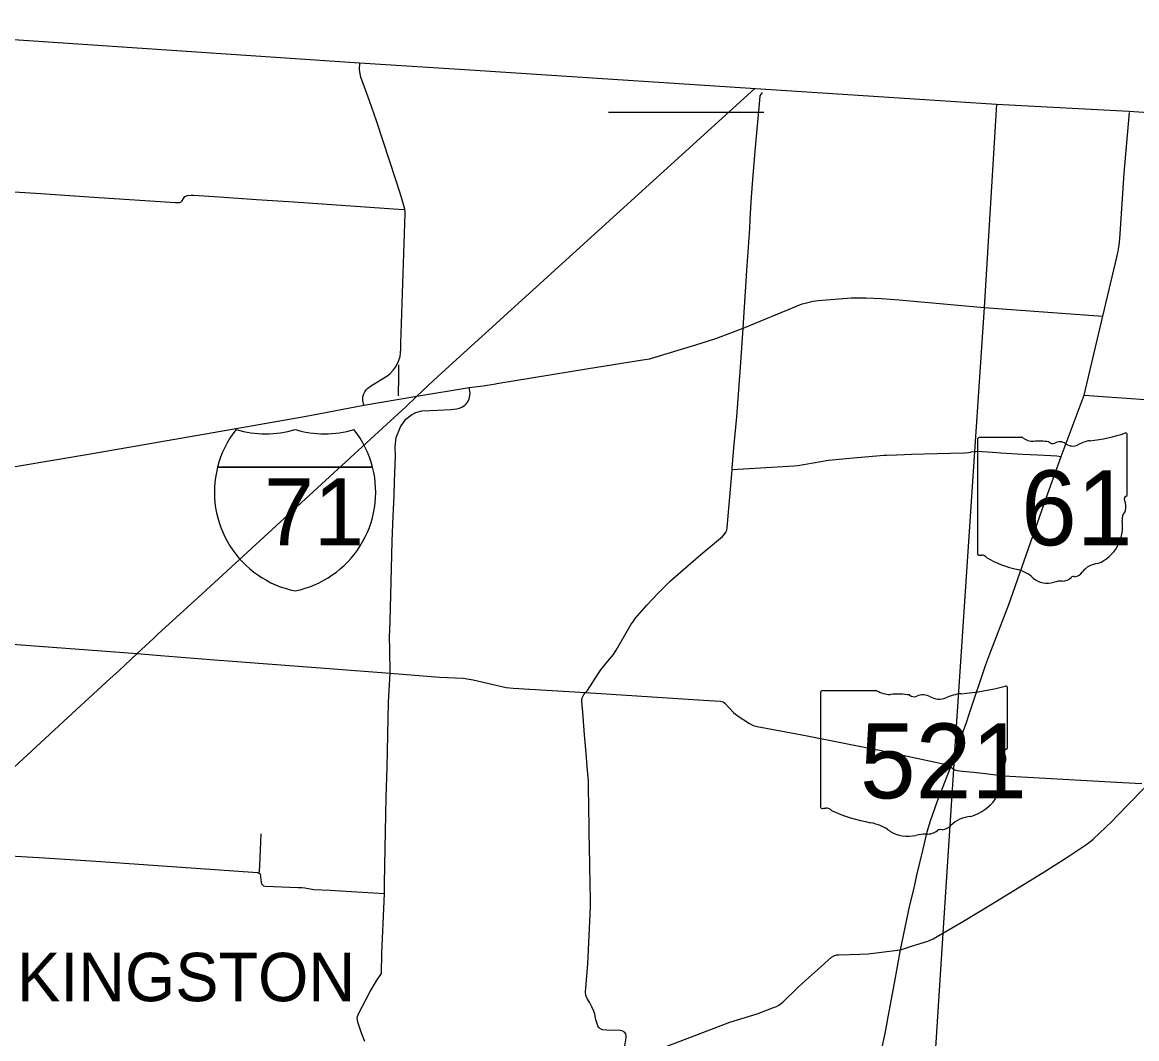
# Model space of a CAD drawing. Extents: x 1729596 to 1925846, y 659247 to 911751.
# Drawn here: x 1855559 to 1876281, y 840189 to 859080 of the extents above; entities that cross this region are included whole.
import ezdxf

# ---------------------------------------------------------------- set-up
doc = ezdxf.new("R2010")
doc.units = 0
for name, color, linetype in [('GM_X_County', 7, 'Continuous'), ('GM_X_County_Road', 7, 'Continuous'), ('GM_X_Interstate_Route', 7, 'Continuous'), ('GM_X_Interstate_Shield', 7, 'Continuous'), ('GM_X_State_Route', 7, 'Continuous'), ('GM_X_State_Shield', 7, 'Continuous'), ('GM_X_Township', 7, 'Continuous'), ('GM_X_Township_Road', 7, 'Continuous'), ('GM_X_Township_Text', 7, 'Continuous')]:
    doc.layers.add(name, color=color, linetype=linetype)

msp = doc.modelspace()

# ---------------------------------------------------------------- linework, layer by layer
at = {"layer": 'GM_X_County'}
msp.add_lwpolyline([(1850615, 859080), (1861827, 858324), (1863977, 858188), (1869100, 857855), (1873671, 857558), (1876143, 857428), (1879641, 857188)], dxfattribs=at)
at = {"layer": 'GM_X_County_Road'}
for points in [[(1864382, 852364), (1866086, 852648), (1867135, 852815), (1867230, 852828), (1867285, 852844), (1868084, 853084), (1868453, 853203), (1868961, 853395), (1869281, 853526), (1870063, 853845), (1870117, 853862), (1870213, 853886), (1870261, 853896), (1870358, 853911), (1870972, 853957), (1871252, 853958), (1871532, 853946), (1871862, 853920), (1872960, 853823), (1873374, 853784)], [(1873374, 853784), (1873447, 853777), (1875479, 853633), (1875652, 853621)], [(1861908, 851967), (1862897, 852129), (1863869, 852294), (1864131, 852325), (1864358, 852360), (1864382, 852364)], [(1862398, 846985), (1862393, 847427), (1862390, 847645), (1862398, 847952), (1862426, 848926), (1862437, 849437), (1862456, 849903), (1862475, 850277), (1862478, 850547), (1862493, 850863), (1862501, 851015), (1862495, 851192), (1862512, 851365), (1862591, 851559), (1862689, 851703), (1862793, 851783), (1862874, 851825), (1862991, 851861), (1863286, 851873), (1863528, 851886), (1863641, 851896), (1863689, 851908), (1863745, 851933), (1863788, 851965), (1863815, 851990), (1863841, 852025), (1863866, 852082), (1863882, 852144), (1863886, 852190), (1863869, 852294)], [(1851992, 850242), (1853696, 850524), (1855503, 850836), (1856828, 851059), (1859214, 851472), (1860807, 851754), (1861908, 851967)], [(1861929, 840138), (1861858, 840312), (1861805, 840480), (1861790, 840535), (1861787, 840580), (1861813, 840652), (1862029, 841063), (1862144, 841266), (1862236, 841398), (1862246, 841780), (1862289, 842748), (1862292, 842889), (1862296, 843070), (1862302, 843409), (1862314, 844036), (1862323, 844679), (1862341, 845231), (1862369, 846442), (1862398, 846985)]]:
    msp.add_lwpolyline(points, dxfattribs=at)
at = {"layer": 'GM_X_Interstate_Route'}
for points in [[(1863205, 852422), (1863294, 852506), (1869179, 857847)], [(1862551, 851804), (1862690, 851932), (1862897, 852129), (1863205, 852422)], [(1858003, 847635), (1858079, 847705), (1858902, 848457), (1860588, 850008), (1861123, 850496), (1862182, 851466), (1862551, 851804)], [(1857351, 847028), (1857695, 847346), (1858003, 847635)], [(1853497, 843457), (1854091, 844035), (1854810, 844689), (1856408, 846161), (1857196, 846884), (1857351, 847028)]]:
    msp.add_lwpolyline(points, dxfattribs=at)
at = {"layer": 'GM_X_Interstate_Shield'}
for p, q in [((1866460, 857408), (1869345, 857408)), ((1859188, 850809), (1862074, 850809)), ((1862074, 850809), (1859188, 850809)), ((1862074, 850809), (1859188, 850809))]:
    msp.add_line(p, q, dxfattribs=at)
for centre, start, end in [((1861006, 850349), 141.669, 165.8066), ((1860083, 853306), 253.0091, 286.9909), ((1861179, 853306), 253.0091, 286.9909), ((1860256, 850349), 14.1934, 38.331), ((1861006, 850349), 165.8066, 258.463), ((1860256, 850349), 281.537, 14.1934)]:
    msp.add_arc(centre, 1875, start, end, dxfattribs=at)
at = {"layer": 'GM_X_State_Route'}
for points in [[(1871531, 839946), (1871607, 840316), (1871659, 840595), (1871776, 841222), (1871888, 841839), (1872065, 842672), (1872135, 842960), (1872195, 843231), (1872309, 843713), (1872385, 844033), (1872444, 844239), (1872573, 844591), (1872823, 845242), (1872889, 845433), (1872993, 845731), (1873113, 846066), (1873172, 846240), (1873478, 847144), (1873548, 847343), (1873901, 848259), (1874595, 850236), (1874875, 851008), (1875301, 852152), (1875652, 853621), (1875910, 854713), (1875935, 854825), (1875954, 854939), (1875967, 855054), (1876050, 856275), (1876144, 857406)], [(1853462, 847664), (1857695, 847346), (1858127, 847314), (1859061, 847239), (1861267, 847070), (1862398, 846985), (1863319, 846906), (1863758, 846887), (1863941, 846861), (1864557, 846719), (1864687, 846705), (1866030, 846621), (1868225, 846483), (1868543, 846460), (1868589, 846449), (1868624, 846426), (1868784, 846250), (1868850, 846195), (1869082, 846046), (1869152, 846012), (1869221, 845989), (1869925, 845860), (1870186, 845810), (1871499, 845553), (1872455, 845346), (1872684, 845295), (1872802, 845263), (1872823, 845242), (1872874, 845201), (1872899, 845188), (1872917, 845181), (1872945, 845174), (1873042, 845161), (1873246, 845142), (1873416, 845122), (1873807, 845072), (1875906, 844954), (1876379, 844930)], [(1875906, 844320), (1876154, 844572), (1876386, 844812), (1876497, 844924), (1876868, 845210), (1877089, 845378), (1877250, 845505), (1877281, 845529), (1877348, 845583), (1877908, 846019)], [(1871888, 841839), (1872092, 841906), (1872394, 841999), (1872499, 842046), (1872678, 842151), (1873057, 842376), (1873560, 842674), (1874539, 843277), (1875001, 843568), (1875337, 843791), (1875406, 843841), (1875471, 843896), (1875822, 844235), (1875906, 844320)]]:
    msp.add_lwpolyline(points, dxfattribs=at)
at = {"layer": 'GM_X_State_Shield'}
for p, q in [((1873321, 851323), (1873321, 849210)), ((1873321, 851323), (1873321, 849210)), ((1874164, 851360), (1873349, 851360)), ((1874164, 851360), (1873349, 851360)), ((1876105, 850307), (1876105, 851412)), ((1876105, 850307), (1876105, 851412)), ((1876105, 850307), (1876105, 850307)), ((1876105, 850307), (1876105, 850307)), ((1873878, 845603), (1873878, 846708)), ((1873878, 845603), (1873878, 846708)), ((1870398, 846620), (1870398, 844506)), ((1870398, 846620), (1870398, 844506)), ((1871452, 846656), (1870432, 846656)), ((1871452, 846656), (1870432, 846656)), ((1873878, 845603), (1873878, 845603)), ((1873878, 845603), (1873878, 845603))]:
    msp.add_line(p, q, dxfattribs=at)
for centre, radius, start, end in [((1873353, 851328), 32.3, 98.1301, 188.1301), ((1873353, 851328), 32.3, 98.1301, 188.1301), ((1874358, 851605), 313, 231.6195, 271.1119), ((1874358, 851605), 313, 231.6195, 271.1119), ((1874462, 850173), 1123, 80.4867, 94.9883), ((1874462, 850173), 1123, 80.4867, 94.9883), ((1874717, 851339), 90.3, 219.7921, 297.1024), ((1874717, 851339), 90.3, 219.7921, 297.1024), ((1874849, 851095), 188, 54.4667, 119.1411), ((1874849, 851095), 188, 54.4667, 119.1411), ((1875490, 850714), 594, 97.3462, 120.7689), ((1875490, 850714), 594, 97.3462, 120.7689), ((1875114, 854241), 2953, 275.8445, 288.9065), ((1875114, 854241), 2953, 275.8445, 288.9065), ((1876075, 851417), 31, 351.8621, 97.738), ((1876075, 851417), 31, 351.8621, 97.738), ((1875092, 851430), 226, 233.8562, 294.8282), ((1875092, 851430), 226, 233.8562, 294.8282), ((1876098, 850225), 48, 107.944, 210.337), ((1876098, 850225), 48, 107.944, 210.337), ((1876072, 850302), 33.2, 289.6038, 7.7341), ((1876072, 850302), 33.2, 289.6038, 7.7341), ((1875793, 850086), 288, 340.033, 23.6496), ((1875793, 850086), 288, 340.033, 23.6496), ((1875279, 849703), 739, 292.3089, 8.9858), ((1875279, 849703), 739, 292.3089, 8.9858), ((1876217, 849844), 210, 136.8065, 186.9296), ((1876217, 849844), 210, 136.8065, 186.9296), ((1873353, 849205), 32.5, 171.9584, 258.3066), ((1873353, 849205), 32.5, 171.9584, 258.3066), ((1873358, 849422), 248, 267.339, 280.6039), ((1873358, 849422), 248, 267.339, 280.6039), ((1873409, 849088), 89.5, 29.7484, 93.2717), ((1873409, 849088), 89.5, 29.7484, 93.2717), ((1874540, 850987), 2132, 240.4129, 257.1985), ((1874540, 850987), 2132, 240.4129, 257.1985), ((1875590, 848617), 404, 94.4031, 142.5768), ((1875590, 848617), 404, 94.4031, 142.5768), ((1873904, 848261), 667, 47.1842, 75.836), ((1873904, 848261), 667, 47.1842, 75.836), ((1875105, 848715), 63.5, 65.7517, 132.6484), ((1875105, 848715), 63.5, 65.7517, 132.6484), ((1875078, 849005), 239, 282.8732, 323.2771), ((1875078, 849005), 239, 282.8732, 323.2771), ((1874625, 849078), 423, 230.7004, 286.2918), ((1874625, 849078), 423, 230.7004, 286.2918), ((1874870, 848347), 348, 85.6951, 111.2099), ((1874870, 848347), 348, 85.6951, 111.2099), ((1874901, 848919), 226, 268.777, 315.5493), ((1874901, 848919), 226, 268.777, 315.5493)]:
    msp.add_arc(centre, radius, start, end, dxfattribs=at)
for centre, major_axis, start_param, end_param in [((1872639, 849537), (3691, 0), 4.814394, 5.042369), ((1872639, 849537), (3691, 0), 4.814394, 5.042369), ((1873840, 846713), (38.7, 0), 6.141152, 7.989035), ((1873840, 846713), (38.7, 0), 6.141152, 7.989035), ((1870438, 846624), (40.3, 0), 1.712693, 3.28349), ((1870438, 846624), (40.3, 0), 1.712693, 3.28349), ((1871694, 846901), (391, 0), 4.042523, 4.731795), ((1871694, 846901), (391, 0), 4.042523, 4.731795), ((1871824, 845470), (1404, 0), 1.404758, 1.657858), ((1871824, 845470), (1404, 0), 1.404758, 1.657858), ((1872143, 846635), (113, 0), 3.836095, 5.185415), ((1872143, 846635), (113, 0), 3.836095, 5.185415), ((1872308, 846391), (235, 0), 0.950623, 2.079405), ((1872308, 846391), (235, 0), 0.950623, 2.079405), ((1872611, 846726), (282, 0), 4.081561, 5.145723), ((1872611, 846726), (282, 0), 4.081561, 5.145723), ((1873109, 846011), (743, 0), 1.699011, 2.107814), ((1873109, 846011), (743, 0), 1.699011, 2.107814), ((1873870, 845522), (60, 0), 1.883978, 3.671073), ((1873870, 845522), (60, 0), 1.883978, 3.671073), ((1873488, 845382), (360, 0), 5.934695, 6.695948), ((1873488, 845382), (360, 0), 5.934695, 6.695948), ((1873837, 845599), (41.5, 0), 5.05454, 6.418171), ((1873837, 845599), (41.5, 0), 5.05454, 6.418171), ((1874017, 845140), (262, 0), 2.387724, 3.262537), ((1874017, 845140), (262, 0), 2.387724, 3.262537), ((1872845, 845000), (923, 0), 5.101752, 6.440018), ((1872845, 845000), (923, 0), 5.101752, 6.440018), ((1870438, 844502), (40.7, 0), 3.00124, 4.508301), ((1870438, 844502), (40.7, 0), 3.00124, 4.508301), ((1870444, 844718), (310, 0), 4.665946, 4.897461), ((1870444, 844718), (310, 0), 4.665946, 4.897461), ((1870508, 844385), (112, 0), 0.519207, 1.627899), ((1870508, 844385), (112, 0), 0.519207, 1.627899), ((1871921, 846283), (2665, 0), 4.195997, 4.488961), ((1871921, 846283), (2665, 0), 4.195997, 4.488961), ((1873235, 843913), (506, 0), 1.647645, 2.488434), ((1873235, 843913), (506, 0), 1.647645, 2.488434), ((1871127, 843557), (834, 0), 0.823519, 1.323587), ((1871127, 843557), (834, 0), 0.823519, 1.323587), ((1872028, 844374), (529, 0), 4.026481, 4.996735), ((1872028, 844374), (529, 0), 4.026481, 4.996735), ((1872373, 844216), (282, 0), 4.691044, 5.507374), ((1872373, 844216), (282, 0), 4.691044, 5.507374), ((1872628, 844011), (79.4, 0), 1.147584, 2.315152), ((1872628, 844011), (79.4, 0), 1.147584, 2.315152), ((1872594, 844302), (298, 0), 4.937069, 5.64225), ((1872594, 844302), (298, 0), 4.937069, 5.64225), ((1872334, 843643), (435, 0), 1.495662, 1.94098), ((1872334, 843643), (435, 0), 1.495662, 1.94098)]:
    msp.add_ellipse(centre, major_axis=major_axis, ratio=0.8, start_param=start_param, end_param=end_param, dxfattribs=at)
at = {"layer": 'GM_X_Township'}
msp.add_lwpolyline([(1850615, 859080), (1861827, 858324), (1863977, 858188), (1869100, 857855), (1873671, 857558), (1873447, 853777), (1873266, 851105), (1872889, 845433), (1872874, 845201), (1872678, 842151), (1872497, 839344), (1872306, 836385), (1871965, 831096), (1871301, 831135), (1870943, 831158), (1868637, 831266), (1861106, 831707), (1859467, 831803), (1858606, 831851), (1854821, 832136)], dxfattribs=at)
at = {"layer": 'GM_X_Township_Road'}
for points in [[(1862600, 853109), (1862679, 855525), (1862678, 855551), (1862670, 855604), (1862621, 855781), (1862579, 855924), (1862511, 856133), (1862144, 857247), (1862016, 857620), (1861855, 858062), (1861842, 858124), (1861831, 858202), (1861835, 858314)], [(1869094, 855406), (1869114, 855750), (1869148, 856242), (1869190, 856752), (1869276, 857636), (1869281, 857713), (1869320, 857773)], [(1851052, 856192), (1851109, 856192), (1851317, 856179), (1852272, 856121), (1852677, 856096), (1855405, 855928), (1855903, 855897), (1856892, 855832)], [(1856892, 855832), (1858408, 855732), (1858481, 855729), (1858507, 855738), (1858528, 855753), (1858558, 855806), (1858584, 855843), (1858630, 855863), (1858699, 855865), (1858740, 855866), (1859219, 855834), (1859911, 855789), (1860608, 855745), (1862639, 855602), (1862670, 855604)], [(1868961, 853395), (1869030, 854466), (1869084, 855249), (1869094, 855406)], [(1866125, 842638), (1866122, 842825), (1866119, 843014), (1866110, 843448), (1866102, 844029), (1866096, 844587), (1866090, 844777), (1866088, 844973), (1866065, 845250), (1866043, 845495), (1866013, 845838), (1865981, 846259), (1865967, 846390), (1865963, 846470), (1865970, 846524), (1865985, 846563), (1865999, 846589), (1866030, 846621), (1866069, 846663), (1866266, 846968), (1866317, 847046), (1866389, 847138), (1866477, 847243), (1866553, 847332), (1866604, 847408), (1866882, 847892), (1866909, 847933), (1866956, 847998), (1867172, 848249), (1867375, 848465), (1867610, 848696), (1868175, 849189), (1868579, 849525), (1868618, 849565), (1868643, 849606), (1868658, 849643), (1868666, 849690), (1868752, 850688), (1868758, 850767), (1868760, 850792), (1868792, 851171), (1868844, 851750), (1868884, 852250), (1868920, 852760), (1868961, 853395)], [(1861908, 851967), (1861890, 852053), (1861889, 852074), (1861893, 852116), (1861897, 852136), (1861910, 852176), (1861929, 852213), (1861940, 852231), (1861953, 852247), (1861967, 852263), (1861987, 852281), (1862055, 852330), (1862353, 852513), (1862401, 852552), (1862464, 852620), (1862501, 852670), (1862532, 852724), (1862557, 852780), (1862583, 852869), (1862593, 852930), (1862597, 853012), (1862600, 853109)], [(1862555, 852138), (1862563, 852502), (1862563, 852712)], [(1875301, 852152), (1877831, 851971)], [(1871629, 851035), (1871821, 851038), (1872096, 851051), (1872573, 851066), (1873080, 851077), (1873153, 851086), (1873189, 851092), (1873201, 851094)], [(1873201, 851094), (1873266, 851105), (1873316, 851109), (1873602, 851093), (1873755, 851081), (1874156, 851056), (1874440, 851043), (1874686, 851029), (1874797, 851021), (1874875, 851008)], [(1868758, 850767), (1869911, 850836), (1869979, 850842), (1870548, 850939), (1871084, 850990), (1871587, 851034), (1871629, 851035)], [(1859959, 843268), (1859968, 843303), (1859973, 843410), (1859989, 843698), (1860002, 843997)], [(1854896, 843613), (1855969, 843548), (1857017, 843480), (1859932, 843277), (1859959, 843268), (1859973, 843260), (1859980, 843245), (1860002, 843098), (1860009, 843067), (1860041, 843030), (1860074, 843024), (1860686, 842999), (1860758, 842996), (1860814, 842991), (1860981, 842964), (1861282, 842947), (1861478, 842937), (1862292, 842889)], [(1866765, 840057), (1866786, 840206), (1866788, 840245), (1866781, 840280), (1866759, 840313), (1866716, 840336), (1866676, 840340), (1866424, 840347), (1866350, 840355), (1866320, 840364), (1866299, 840377), (1866280, 840396), (1866263, 840426), (1866226, 840542), (1866202, 840647), (1866186, 840698), (1866148, 840779), (1866109, 840853), (1866060, 840934), (1866038, 840989), (1866033, 841051), (1866073, 841581), (1866099, 842105), (1866125, 842638)], [(1866665, 839615), (1866674, 839624), (1866777, 839711), (1866913, 839811), (1868052, 840243), (1868716, 840498), (1869221, 840653), (1869529, 840766), (1869582, 840790), (1869627, 840814), (1869702, 840869), (1869986, 841148), (1870122, 841273), (1870349, 841472), (1870605, 841706), (1870651, 841731), (1870706, 841746), (1870745, 841748), (1871135, 841758), (1871285, 841769), (1871833, 841832), (1871888, 841839)]]:
    msp.add_lwpolyline(points, dxfattribs=at)

# ---------------------------------------------------------------- texts
at = {"layer": 'GM_X_Interstate_Shield'}
msp.add_text('71', height=1250, dxfattribs=at).set_placement((1860053, 849356))
at = {"layer": 'GM_X_State_Shield'}
for s, p in [('61', (1874131, 849359)), ('61', (1874131, 849359)), ('521', (1871135, 844656)), ('521', (1871135, 844656))]:
    msp.add_text(s, height=1392.2, dxfattribs=at).set_placement(p)
at = {"layer": 'GM_X_Township_Text'}
msp.add_text('KINGSTON', height=900, rotation=0, dxfattribs=at).set_placement((1855462, 840885))

doc.saveas('drawing.dxf')
